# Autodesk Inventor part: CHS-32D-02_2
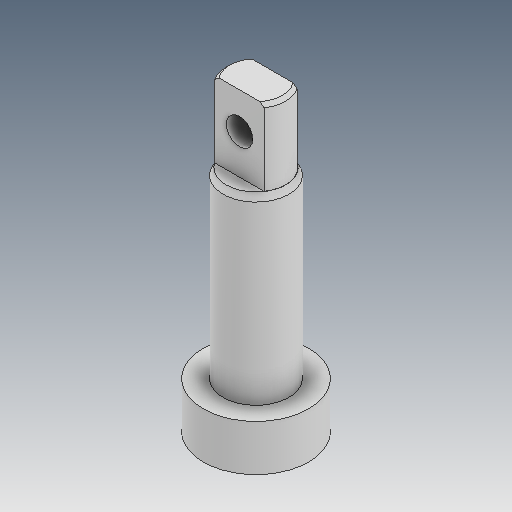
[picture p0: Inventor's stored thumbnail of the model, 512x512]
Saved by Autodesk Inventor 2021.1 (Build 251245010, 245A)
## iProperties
Created: 2021-05
Part Number: CHS-32D-02_2
Material: Ogólny
Document SubType Name: Modeling
Designer: user
Density: 1 g/cm^3
Appearance: Domyślna
Author: user
Revision Number: ÈÎºÎ
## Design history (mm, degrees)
feature "ÊäÈë1"
feature "ÊäÈë2"
node "Bryła1"
node "Bryła2"
